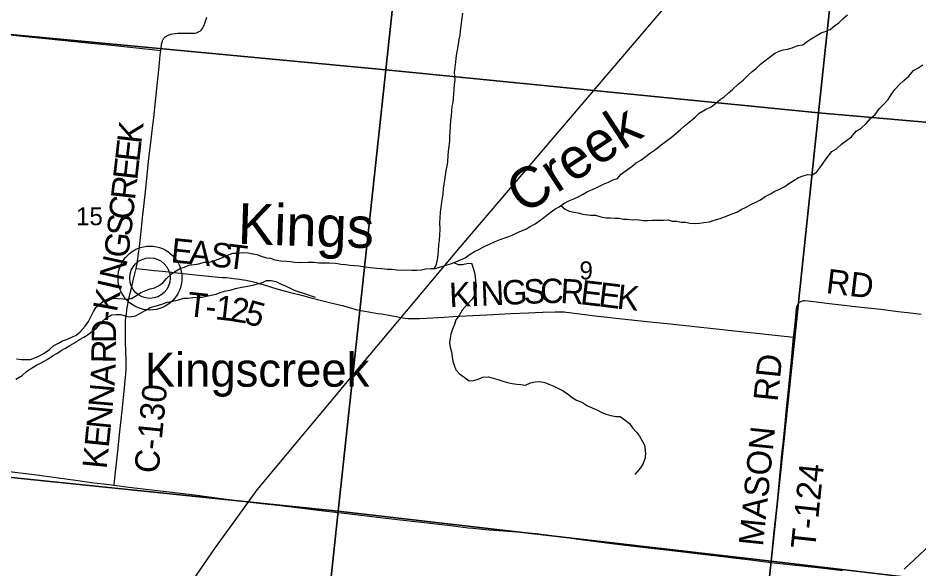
# Model space of a CAD drawing. Extents: x 0 to 1101, y 0 to 440.
# Drawn here: x 842.072 to 844.169, y 370.546 to 371.828 of the extents above; entities that cross this region are included whole.
import ezdxf

# ---------------------------------------------------------------- set-up
doc = ezdxf.new("R2010")
doc.units = 0
for name, color, linetype in [('GM_X_County_Road', 7, 'Continuous'), ('GM_X_County_Road_Text', 7, 'Continuous'), ('GM_X_Minor_River', 7, 'Continuous'), ('GM_X_Minor_River_Text', 7, 'Continuous'), ('GM_X_Rail_Line', 7, 'Continuous'), ('GM_X_Section', 7, 'Continuous'), ('GM_X_Section_Text', 7, 'Continuous'), ('GM_X_State_Route', 7, 'Continuous'), ('GM_X_Township_Road', 7, 'Continuous'), ('GM_X_Township_Road_Text', 7, 'Continuous'), ('GM_X_Unincorporated', 7, 'Continuous'), ('GM_X_Unincorporated_Location', 7, 'Continuous'), ('GM_X_Unincorporated_Text', 7, 'Continuous')]:
    doc.layers.add(name, color=color, linetype=linetype)

msp = doc.modelspace()

# ---------------------------------------------------------------- linework, layer by layer
at = {"layer": 'GM_X_County_Road'}
for points in [[(842.4044, 371.7528), (842.4048, 371.7566), (842.4053, 371.7605), (842.4058, 371.7644), (842.4062, 371.767), (842.4067, 371.7697), (842.4073, 371.7722), (842.408, 371.7743), (842.4085, 371.7757), (842.4092, 371.7771), (842.4099, 371.7782), (842.4107, 371.7796), (842.4116, 371.7809), (842.4125, 371.782), (842.4138, 371.7832), (842.4147, 371.7841), (842.4159, 371.7851), (842.417, 371.7859), (842.4186, 371.7869), (842.4202, 371.7877), (842.4217, 371.7885), (842.4235, 371.7892), (842.4261, 371.7901), (842.4281, 371.7907), (842.4322, 371.7917), (842.4377, 371.7924), (842.4432, 371.7928), (842.4532, 371.7929), (842.47, 371.7927), (842.4758, 371.7926), (842.4795, 371.7926), (842.483, 371.793), (842.4873, 371.7939), (842.4908, 371.795), (842.494, 371.7964), (842.4968, 371.7984), (842.4994, 371.8008), (842.5016, 371.8039), (842.504, 371.8081), (842.5051, 371.8107), (842.5064, 371.8139), (842.5119, 371.8305)], [(842.3472, 371.2455), (842.3493, 371.2567), (842.3511, 371.2686), (842.3528, 371.2803), (842.3546, 371.2956), (842.3571, 371.3178), (842.3593, 371.3391), (842.3621, 371.3632), (842.3642, 371.3824), (842.3664, 371.4033), (842.3679, 371.417), (842.3718, 371.4546), (842.3767, 371.5018), (842.3812, 371.5389), (842.3843, 371.5658), (842.3881, 371.5968), (842.3954, 371.6645), (842.3969, 371.6792), (842.4007, 371.7148), (842.4032, 371.7421), (842.4044, 371.7528)], [(842.2958, 370.7411), (842.2969, 370.7506), (842.3052, 370.8272), (842.3086, 370.8593), (842.3142, 370.9143), (842.3189, 370.9601), (842.3222, 370.9925), (842.3228, 370.9993), (842.3231, 371.0034), (842.3235, 371.0084), (842.3238, 371.0142), (842.324, 371.019), (842.324, 371.0239), (842.324, 371.0298), (842.3238, 371.0363), (842.3236, 371.0407), (842.3234, 371.045), (842.3231, 371.0513), (842.3228, 371.0594), (842.3225, 371.0677), (842.322, 371.0797), (842.322, 371.0922), (842.3219, 371.1036), (842.3222, 371.1122), (842.3226, 371.1221), (842.3233, 371.1319), (842.3242, 371.1396), (842.3253, 371.1473), (842.3264, 371.1547), (842.3275, 371.1618), (842.3293, 371.171), (842.3325, 371.1847), (842.3368, 371.2026), (842.3404, 371.2174), (842.3472, 371.2455)]]:
    msp.add_lwpolyline(points, dxfattribs=at)
at = {"layer": 'GM_X_Minor_River'}
for points in [[(843.0416, 371.2457), (843.0457, 371.2552), (843.0485, 371.2658), (843.0497, 371.2769), (843.0506, 371.2883), (843.0518, 371.2993), (843.0531, 371.3123), (843.0539, 371.3229), (843.0544, 371.337), (843.0542, 371.3515), (843.0543, 371.3625), (843.0552, 371.3766), (843.0572, 371.3876), (843.0588, 371.3994), (843.0604, 371.4093), (843.0613, 371.4192), (843.0625, 371.4313), (843.0641, 371.4412), (843.0654, 371.4511), (843.067, 371.4625), (843.0686, 371.4732), (843.071, 371.4834), (843.0722, 371.4933), (843.0735, 371.5081), (843.074, 371.518), (843.0752, 371.5298), (843.0768, 371.5423), (843.0769, 371.553), (843.0778, 371.564), (843.079, 371.5762), (843.0796, 371.5899), (843.0808, 371.6002), (843.0816, 371.6112), (843.0829, 371.6222), (843.0845, 371.6317), (843.0853, 371.6416), (843.0866, 371.6518), (843.0871, 371.6617), (843.0879, 371.6731), (843.0892, 371.6834), (843.0889, 371.6929), (843.0878, 371.7024), (843.0894, 371.7131), (843.0911, 371.7256), (843.0919, 371.7351), (843.0935, 371.7458), (843.0959, 371.7575), (843.0971, 371.7674), (843.0991, 371.778), (843.1008, 371.7883), (843.102, 371.7985), (843.1036, 371.8099), (843.1057, 371.8274), (843.1077, 371.8396)], [(843.1347, 371.2848), (843.1442, 371.2896), (843.1588, 371.2971), (843.1695, 371.3016), (843.1825, 371.3079), (843.194, 371.3131), (843.2077, 371.3176), (843.2203, 371.3224), (843.2318, 371.3276), (843.244, 371.3332), (843.2539, 371.3365), (843.2643, 371.3433), (843.2754, 371.3492), (843.2892, 371.3586), (843.2987, 371.3661), (843.3106, 371.3755), (843.3217, 371.3834), (843.3313, 371.389), (843.3424, 371.3969), (843.3539, 371.4025), (843.3657, 371.4077), (843.3772, 371.4129), (843.3872, 371.4182), (843.3975, 371.4242), (843.4093, 371.429), (843.4223, 371.4357), (843.435, 371.4417), (843.4464, 371.4465), (843.4575, 371.4517), (843.4671, 371.4547), (843.4759, 371.4645), (843.4855, 371.4716), (843.5012, 371.4832), (843.5108, 371.4915), (843.5215, 371.4971), (843.5342, 371.5069), (843.5445, 371.5144), (843.5556, 371.5219), (843.5687, 371.5332), (843.5802, 371.5418), (843.5924, 371.5504), (843.6032, 371.5591), (843.6131, 371.5681), (843.6227, 371.5764), (843.6342, 371.5858), (843.6481, 371.5974), (843.6577, 371.6065), (843.6722, 371.6155), (843.6852, 371.6218), (843.6955, 371.6289), (843.7059, 371.6383), (843.7159, 371.6451), (843.7255, 371.6537), (843.7351, 371.662), (843.7485, 371.674), (843.7596, 371.6838), (843.77, 371.6936), (843.7804, 371.7038), (843.7899, 371.7105), (843.8003, 371.7211), (843.8099, 371.7282), (843.8203, 371.7365), (843.8325, 371.7455), (843.8432, 371.7507), (843.8528, 371.7544), (843.8631, 371.7558), (843.8741, 371.7591), (843.8868, 371.7639), (843.8986, 371.7661), (843.9085, 371.7736), (843.9181, 371.7796), (843.93, 371.7867), (843.9411, 371.7934), (843.951, 371.7968), (843.9621, 371.8012), (843.9721, 371.8102), (843.9824, 371.817), (843.9928, 371.8271), (844.0028, 371.8358)], [(843.3356, 371.3921), (843.3457, 371.3832), (843.3552, 371.3789), (843.3655, 371.3761), (843.3757, 371.3749), (843.3867, 371.3721), (843.4035, 371.3693), (843.416, 371.3691), (843.4286, 371.3656), (843.4407, 371.3636), (843.4506, 371.3635), (843.4613, 371.3626), (843.4712, 371.3625), (843.4811, 371.3605), (843.4906, 371.3604), (843.502, 371.3588), (843.5134, 371.359), (843.5275, 371.357), (843.5374, 371.3569), (843.5477, 371.3575), (843.5599, 371.3582), (843.5743, 371.3576), (843.585, 371.3583), (843.5949, 371.3552), (843.6055, 371.3554), (843.6158, 371.353), (843.6261, 371.3529), (843.6356, 371.3509), (843.6481, 371.3504), (843.658, 371.3511), (843.6683, 371.3521), (843.6817, 371.3543), (843.692, 371.3576), (843.7061, 371.3616), (843.716, 371.3657), (843.734, 371.3724), (843.7447, 371.3768), (843.7554, 371.3825), (843.7665, 371.388), (843.7776, 371.394), (843.7894, 371.4), (843.8005, 371.4048), (843.8112, 371.4127), (843.8235, 371.4194), (843.8331, 371.4251), (843.843, 371.4295), (843.8564, 371.4362), (843.8663, 371.4434), (843.8786, 371.4505), (843.8889, 371.4568), (843.8996, 371.4609), (843.9095, 371.4642), (843.9213, 371.4634), (843.9309, 371.4701), (843.9379, 371.4799), (843.9456, 371.4905), (843.9529, 371.5007), (843.9664, 371.5177), (843.9771, 371.5241), (843.989, 371.535), (844.0001, 371.5429), (844.0116, 371.5515), (844.0224, 371.5647), (844.0343, 371.5718), (844.0458, 371.5824), (844.0565, 371.5941), (844.0673, 371.6038), (844.0765, 371.6171), (844.0865, 371.6272), (844.0969, 371.6386), (844.105, 371.651), (844.1131, 371.6616), (844.1239, 371.6737), (844.1335, 371.6831), (844.145, 371.6929), (844.1562, 371.7061), (844.1661, 371.7117), (844.1776, 371.7196)], [(842.0683, 371.0353), (842.0801, 371.0337), (842.0896, 371.034), (842.101, 371.0335), (842.1113, 371.0372), (842.1224, 371.042), (842.1328, 371.0484), (842.145, 371.0567), (842.1554, 371.0661), (842.1661, 371.0713), (842.1757, 371.077), (842.1852, 371.0803), (842.1974, 371.0855), (842.2074, 371.0904), (842.217, 371.0983), (842.2281, 371.1115), (842.2362, 371.1221), (842.2424, 371.1346), (842.2478, 371.1456), (842.2536, 371.1555), (842.2632, 371.163), (842.2728, 371.1713), (842.2827, 371.1743), (842.2934, 371.1761), (842.3037, 371.1756), (842.317, 371.1751), (842.3269, 371.1738), (842.3364, 371.1756), (842.3479, 371.1828), (842.3583, 371.1892), (842.3697, 371.1944), (842.3797, 371.1981), (842.3896, 371.2007), (842.3991, 371.2048), (842.4091, 371.2119), (842.4176, 371.2221), (842.4295, 371.2327), (842.4398, 371.2402), (842.4501, 371.2458), (842.4597, 371.2484), (842.47, 371.2528), (842.4818, 371.255), (842.4929, 371.2564), (842.5055, 371.2601), (842.5169, 371.26), (842.5276, 371.2629), (842.5383, 371.2667), (842.5501, 371.2715), (842.5597, 371.2763), (842.5719, 371.2808), (842.5833, 371.2807), (842.5959, 371.2829), (842.6081, 371.2816), (842.6184, 371.2796), (842.6279, 371.2776), (842.6381, 371.2741), (842.6503, 371.2701), (842.6601, 371.2693), (842.67, 371.2658), (842.6841, 371.2633), (842.6966, 371.2628), (842.7061, 371.2616), (842.7157, 371.26), (842.7274, 371.2591), (842.7473, 371.2604), (842.7613, 371.2599), (842.7724, 371.2587), (842.7857, 371.2589), (842.7956, 371.2584), (842.8112, 371.2579), (842.8241, 371.2555), (842.834, 371.2546), (842.8454, 371.2534), (842.8549, 371.2525), (842.8656, 371.2513), (842.8797, 371.2492), (842.8918, 371.2476), (842.9074, 371.2463), (842.9192, 371.245), (842.9314, 371.2442), (842.9428, 371.244), (842.9531, 371.242), (842.9637, 371.2412), (842.9744, 371.2422), (842.9881, 371.2417), (843.0003, 371.2416), (843.0102, 371.2426), (843.0216, 371.2444), (843.0327, 371.2451), (843.0426, 371.2457), (843.0533, 371.2483), (843.0659, 371.2523), (843.0808, 371.2571), (843.0911, 371.2608), (843.1018, 371.2653), (843.1125, 371.2705), (843.1243, 371.2784), (843.1347, 371.2848)], [(843.0867, 371.2593), (843.0963, 371.2543), (843.1062, 371.2546), (843.1169, 371.2572), (843.1272, 371.2574), (843.1317, 371.246), (843.1346, 371.236), (843.1357, 371.2261), (843.1371, 371.2162), (843.1382, 371.2059), (843.1377, 371.1953), (843.1357, 371.1858), (843.1291, 371.1744), (843.118, 371.1627), (843.1057, 371.1484), (843.0991, 371.1358), (843.0914, 371.1256), (843.0879, 371.115), (843.0836, 371.1044), (843.0797, 371.0926), (843.0781, 371.0831), (843.0764, 371.0732), (843.0782, 371.0625), (843.0812, 371.0515), (843.0826, 371.04), (843.0844, 371.0297), (843.0874, 371.0202), (843.0911, 371.0098), (843.0998, 371.0002), (843.1107, 370.9925), (843.1217, 370.9844), (843.1328, 370.9847), (843.1431, 370.988), (843.1541, 370.9925), (843.1671, 370.9931), (843.1777, 370.9903), (843.1887, 370.9868), (843.2001, 370.9829), (843.2115, 370.9801), (843.2225, 370.9777), (843.2328, 370.9764), (843.2427, 370.9752), (843.253, 370.9743), (843.2652, 370.9795), (843.2755, 370.9817), (843.2869, 370.9824), (843.298, 370.98), (843.3078, 370.9761), (843.3192, 370.9718), (843.3287, 370.9671), (843.3412, 370.9605), (843.351, 370.9536), (843.362, 370.9454), (843.3718, 370.9392), (843.3855, 370.9334), (843.3972, 370.926), (843.4086, 370.921), (843.4204, 370.9159), (843.4306, 370.9101), (843.4408, 370.9062), (843.4518, 370.9034), (843.4636, 370.9014), (843.4735, 370.9013), (843.4852, 370.8924), (843.4955, 370.8851), (843.5026, 370.8747), (843.5117, 370.8647), (843.5184, 370.8551), (843.5244, 370.8448), (843.53, 370.8344), (843.5315, 370.8237), (843.5321, 370.8134), (843.5313, 370.8024), (843.527, 370.7914), (843.5208, 370.7816), (843.5123, 370.7714), (843.5073, 370.7661)], [(842.0671, 370.9877), (842.082, 370.9963), (842.0916, 371.0061), (842.1031, 371.0133), (842.115, 371.0204), (842.1261, 371.0256), (842.1402, 371.0339), (842.1521, 371.0421), (842.1621, 371.0478), (842.1728, 371.0549), (842.1827, 371.0598), (842.1927, 371.0661), (842.2034, 371.0721), (842.2149, 371.08), (842.2252, 371.0853), (842.2352, 371.092), (842.2448, 371.0992), (842.2547, 371.1067), (842.267, 371.1211), (842.2766, 371.1297), (842.2904, 371.1372), (842.3003, 371.1383), (842.3114, 371.1382), (842.3216, 371.135), (842.3311, 371.133), (842.3456, 371.1356), (842.3575, 371.1415), (842.3693, 371.1487), (842.3797, 371.1547), (842.3915, 371.1576), (842.4071, 371.1624), (842.4194, 371.1668), (842.4293, 371.1683), (842.4453, 371.1723), (842.4571, 371.1764), (842.4678, 371.1763), (842.4789, 371.1777), (842.4895, 371.1784), (842.4998, 371.1786), (842.5105, 371.1812), (842.5219, 371.183), (842.533, 371.1856), (842.5429, 371.1897), (842.5525, 371.1926), (842.5662, 371.1951), (842.5784, 371.1985), (842.5891, 371.2014), (842.6013, 371.2032), (842.6108, 371.205), (842.6208, 371.2072), (842.641, 371.2131), (842.6505, 371.2176), (842.6612, 371.2178), (842.6722, 371.2151), (842.6828, 371.21), (842.6961, 371.2042), (842.7151, 371.1952), (842.7261, 371.1909), (842.7367, 371.1878), (842.7462, 371.1846), (842.7564, 371.1807), (842.7633, 371.1784)]]:
    msp.add_lwpolyline(points, dxfattribs=at)
at = {"layer": 'GM_X_Rail_Line'}
for points in [[(841.4728, 368.6426), (841.5036, 368.6835), (841.5374, 368.7376), (841.6188, 368.8614), (841.6632, 368.9407), (841.7044, 369.0211), (841.7667, 369.1427), (842.0077, 369.6134), (842.282, 370.1444), (842.3817, 370.3472), (842.4321, 370.4445), (842.4792, 370.5194), (842.5317, 370.5965), (842.5789, 370.6613), (842.6287, 370.7304), (842.8514, 370.9969), (843.1012, 371.295), (843.5697, 371.844), (844.1633, 372.5544), (844.2567, 372.6675)], [(844.1346, 370.5459), (844.3997, 370.7937)]]:
    msp.add_lwpolyline(points, dxfattribs=at)
at = {"layer": 'GM_X_Section'}
for points in [[(843.0306, 372.6604), (842.9284, 371.7073), (841.873, 371.8071), (841.9909, 372.7687)], [(843.0306, 372.6604), (844.0354, 372.5461), (843.9352, 371.6074), (842.9284, 371.7073)], [(844.0354, 372.5461), (844.1659, 372.5327), (844.2091, 372.3504), (844.2884, 372.001), (844.3881, 371.5681), (843.9352, 371.6074)], [(841.873, 371.8071), (842.9284, 371.7073), (842.8172, 370.6809), (841.7775, 370.7877)], [(842.9284, 371.7073), (843.9352, 371.6074), (843.8246, 370.5643), (842.8172, 370.6809)], [(843.9352, 371.6074), (844.3881, 371.5681), (844.393, 371.547), (844.6414, 370.468), (843.8246, 370.5643)], [(842.8172, 370.6809), (842.711, 369.6847), (841.6791, 369.8096), (841.7775, 370.7877)], [(842.8172, 370.6809), (843.8246, 370.5643), (843.7228, 369.5896), (842.711, 369.6847)], [(843.8246, 370.5643), (844.6414, 370.468), (844.8139, 369.7283), (844.7837, 369.4496), (843.7228, 369.5896)]]:
    msp.add_lwpolyline(points, close=True, dxfattribs=at)
at = {"layer": 'GM_X_State_Route'}
for points in [[(841.7803, 370.7952), (841.7843, 370.7954), (841.8116, 370.7966), (841.8258, 370.7967), (841.8389, 370.7966), (841.8537, 370.7959), (841.8723, 370.7947), (841.8939, 370.7927), (841.9199, 370.7898), (841.9772, 370.7827), (842.045, 370.774), (842.1097, 370.7659), (842.1491, 370.7606), (842.2057, 370.7529), (842.2494, 370.7469), (842.2778, 370.7433), (842.2958, 370.7411)], [(842.2958, 370.7411), (842.3302, 370.7369), (842.4228, 370.7258), (842.4826, 370.7188), (842.5627, 370.7083), (842.6329, 370.6994), (842.6835, 370.6939), (842.7588, 370.6849), (842.7841, 370.6818), (842.8383, 370.6754), (842.9152, 370.6663), (842.9892, 370.6577), (843.0182, 370.6543), (843.0515, 370.6503), (843.0848, 370.6463), (843.1194, 370.6422), (843.1305, 370.6411), (843.1689, 370.6377), (843.2238, 370.6335), (843.2686, 370.6299), (843.2787, 370.6289), (843.2902, 370.6276), (843.3142, 370.6242), (843.3547, 370.6184), (843.3873, 370.6138), (843.4544, 370.6054), (843.4994, 370.5999), (843.5457, 370.5948), (843.5877, 370.5898), (843.6333, 370.5843), (843.6722, 370.5797), (843.7123, 370.575), (843.7438, 370.5714), (843.7765, 370.5675), (843.7999, 370.5647), (843.8251, 370.5617), (843.8382, 370.5602), (843.8974, 370.5537), (843.9535, 370.5474), (843.9911, 370.5426)]]:
    msp.add_lwpolyline(points, dxfattribs=at)
at = {"layer": 'GM_X_Township_Road'}
for points in [[(841.8752, 371.8059), (841.927, 371.8011), (841.9901, 371.7949), (842.0365, 371.7905), (842.0977, 371.7846), (842.2426, 371.7699), (842.2828, 371.7658), (842.3832, 371.7551), (842.4044, 371.7528)], [(842.3472, 371.2455), (842.362, 371.2439), (842.3895, 371.241), (842.4083, 371.239), (842.4701, 371.2324), (842.4932, 371.2301), (842.5234, 371.227), (842.5389, 371.2255), (842.548, 371.2247), (842.5563, 371.2241), (842.5629, 371.2234), (842.5686, 371.2229), (842.5734, 371.2224), (842.5811, 371.2214), (842.5875, 371.2205), (842.5967, 371.2192), (842.6029, 371.2181), (842.609, 371.217), (842.614, 371.216), (842.6198, 371.2146), (842.626, 371.2128), (842.6329, 371.2107), (842.6424, 371.2078), (842.677, 371.1976), (842.7034, 371.1904), (842.7346, 371.1822), (842.7509, 371.178), (842.775, 371.1719), (842.7937, 371.1674), (842.8268, 371.159), (842.846, 371.1537), (842.8586, 371.1503), (842.8744, 371.1469), (842.8927, 371.1435), (842.9099, 371.1408), (842.9178, 371.1396), (842.9356, 371.1367), (842.9601, 371.1324), (842.9729, 371.1301), (842.9791, 371.1293), (842.9853, 371.1288), (842.9966, 371.1288), (843.0065, 371.1291), (843.0227, 371.13), (843.0636, 371.1323), (843.0847, 371.1334), (843.1307, 371.1357), (843.1629, 371.1375), (843.2187, 371.1406), (843.2603, 371.1426), (843.2761, 371.1431), (843.2938, 371.1438), (843.3223, 371.1446), (843.3307, 371.1445), (843.3373, 371.1445), (843.3429, 371.1443), (843.348, 371.1439), (843.3547, 371.1433), (843.3607, 371.1425), (843.3726, 371.1409), (843.4155, 371.1352), (843.4853, 371.1274), (843.5502, 371.1205), (843.5904, 371.1164), (843.6472, 371.1103), (843.7325, 371.1011), (843.8344, 371.0904), (843.8771, 371.086)], [(843.8771, 371.086), (843.8776, 371.0906), (843.8783, 371.0964), (843.8801, 371.1106), (843.8817, 371.1253), (843.8841, 371.152), (843.8848, 371.1564), (843.8859, 371.1601), (843.8867, 371.1618), (843.8885, 371.1646), (843.8908, 371.1669), (843.8926, 371.1682), (843.8952, 371.1696), (843.8984, 371.1705), (843.9009, 371.1709), (843.9042, 371.1711), (843.9111, 371.1704), (843.9364, 371.1673), (843.9598, 371.1642), (843.9948, 371.1602), (844.0277, 371.1564), (844.0802, 371.1506), (844.1209, 371.1457), (844.1492, 371.1421), (844.1739, 371.1392)], [(843.8251, 370.5617), (843.8258, 370.5689), (843.8266, 370.5761), (843.8273, 370.5846), (843.8283, 370.5957), (843.8299, 370.6105), (843.8322, 370.6352), (843.8342, 370.655), (843.8356, 370.668), (843.8401, 370.7112), (843.8427, 370.7371), (843.8477, 370.7872), (843.8501, 370.8138), (843.8526, 370.8386), (843.8549, 370.8608), (843.858, 370.893), (843.8598, 370.9109), (843.8684, 370.9937), (843.8732, 371.0407), (843.8771, 371.086)]]:
    msp.add_lwpolyline(points, dxfattribs=at)
at = {"layer": 'GM_X_Unincorporated'}
for radius in [0.0744, 0.0472]:
    msp.add_circle((842.3792, 371.2231), radius, dxfattribs=at)
at = {"layer": 'GM_X_Unincorporated_Location'}
msp.add_line((842.3792, 371.2231), (842.3792, 371.2231), dxfattribs=at)

# ---------------------------------------------------------------- texts
at = {"layer": 'GM_X_County_Road_Text'}
for s, height, rotation, p in [('K', 0.0568, 83.5974, (842.359, 371.5341)), ('E', 0.0568, 83.5969, (842.3543, 371.4919)), ('E', 0.0568, 83.5969, (842.3495, 371.4497)), ('R', 0.0568, 83.5987, (842.3443, 371.4033)), ('C', 0.0568, 83.5987, (842.3391, 371.3569)), ('S', 0.0568, 83.5377, (842.3348, 371.3187)), ('G', 0.0568, 82.1002, (842.3277, 371.2677)), ('N', 0.0568, 77.6063, (842.3162, 371.2141)), ('I', 0.0568, 77.185, (842.3109, 371.1909)), ('K', 0.0568, 79.3638, (842.3018, 371.1423)), ('-', 0.0568, 85.2091, (842.3, 371.1205)), ('D', 0.0568, 89.831, (842.2999, 371.0718)), ('R', 0.0568, 89.6123, (842.2996, 371.0249)), ('A', 0.0568, 86.9826, (842.2969, 370.9721)), ('N', 0.0568, 85.0315, (842.2924, 370.9202)), ('C-130', 0.05682, 84.2353, (842.3988, 370.7671)), ('N', 0.0568, 84.3605, (842.2874, 370.8697)), ('E', 0.0568, 84.338, (842.2832, 370.8274)), ('K', 0.0568, 84.3409, (842.2783, 370.7776))]:
    msp.add_text(s, height=height, rotation=rotation, dxfattribs=at).set_placement(p)
at = {"layer": 'GM_X_Minor_River_Text'}
for s, height, rotation, p in [('Creek', 0.09461, 33.1206, (843.2491, 371.3695)), ('Kings', 0.0947, 358.1764, (842.5827, 371.3027))]:
    msp.add_text(s, height=height, rotation=rotation, dxfattribs=at).set_placement(p)
at = {"layer": 'GM_X_Section_Text'}
for s, height, p in [('15', 0.04186, (842.2072, 371.346)), ('9', 0.0419, (843.3789, 371.22))]:
    msp.add_text(s, height=height, rotation=0, dxfattribs=at).set_placement(p)
at = {"layer": 'GM_X_Township_Road_Text'}
for s, height, rotation, p in [('E', 0.0568, 354.1875, (842.4262, 371.2601)), ('A', 0.0568, 354.1836, (842.4684, 371.2558)), ('S', 0.0568, 353.9547, (842.5181, 371.2508)), ('T', 0.0568, 353.027, (842.556, 371.2468)), ('RD', 0.05682, 353.1707, (843.9509, 371.1884)), ('K', 0.0568, 2.496, (843.0767, 371.1552)), ('I', 0.0568, 2.4947, (843.1267, 371.1574)), ('N', 0.0568, 2.4952, (843.15, 371.1584)), ('G', 0.0568, 2.496, (843.1999, 371.1606)), ('S', 0.0568, 2.4858, (843.2499, 371.1628)), ('C', 0.0568, 1.0499, (843.2878, 371.1644)), ('R', 0.0568, 356.4383, (843.3333, 371.1653)), ('E', 0.0568, 353.2216, (843.379, 371.1625)), ('E', 0.0568, 353.1137, (843.4212, 371.1575)), ('T', 0.0568, 353.666, (842.4639, 371.1349)), ('K', 0.0568, 353.9936, (843.4643, 371.1523)), ('1', 0.0568, 353.565, (842.5293, 371.1276)), ('2', 0.0568, 350.7225, (842.5634, 371.1238)), ('5', 0.0568, 344.6687, (842.5964, 371.1185)), ('-', 0.0568, 353.6408, (842.5061, 371.1302)), ('RD', 0.05682, 84.0932, (843.84, 370.9344)), ('MASON', 0.05682, 84.139, (843.8058, 370.5976)), ('T-124', 0.05682, 83.9617, (843.927, 370.591))]:
    msp.add_text(s, height=height, rotation=rotation, dxfattribs=at).set_placement(p)
at = {"layer": 'GM_X_Unincorporated_Text'}
msp.add_text('Kingscreek', height=0.07898, rotation=0, dxfattribs=at).set_placement((842.3672, 370.9704))

doc.saveas('drawing.dxf')
